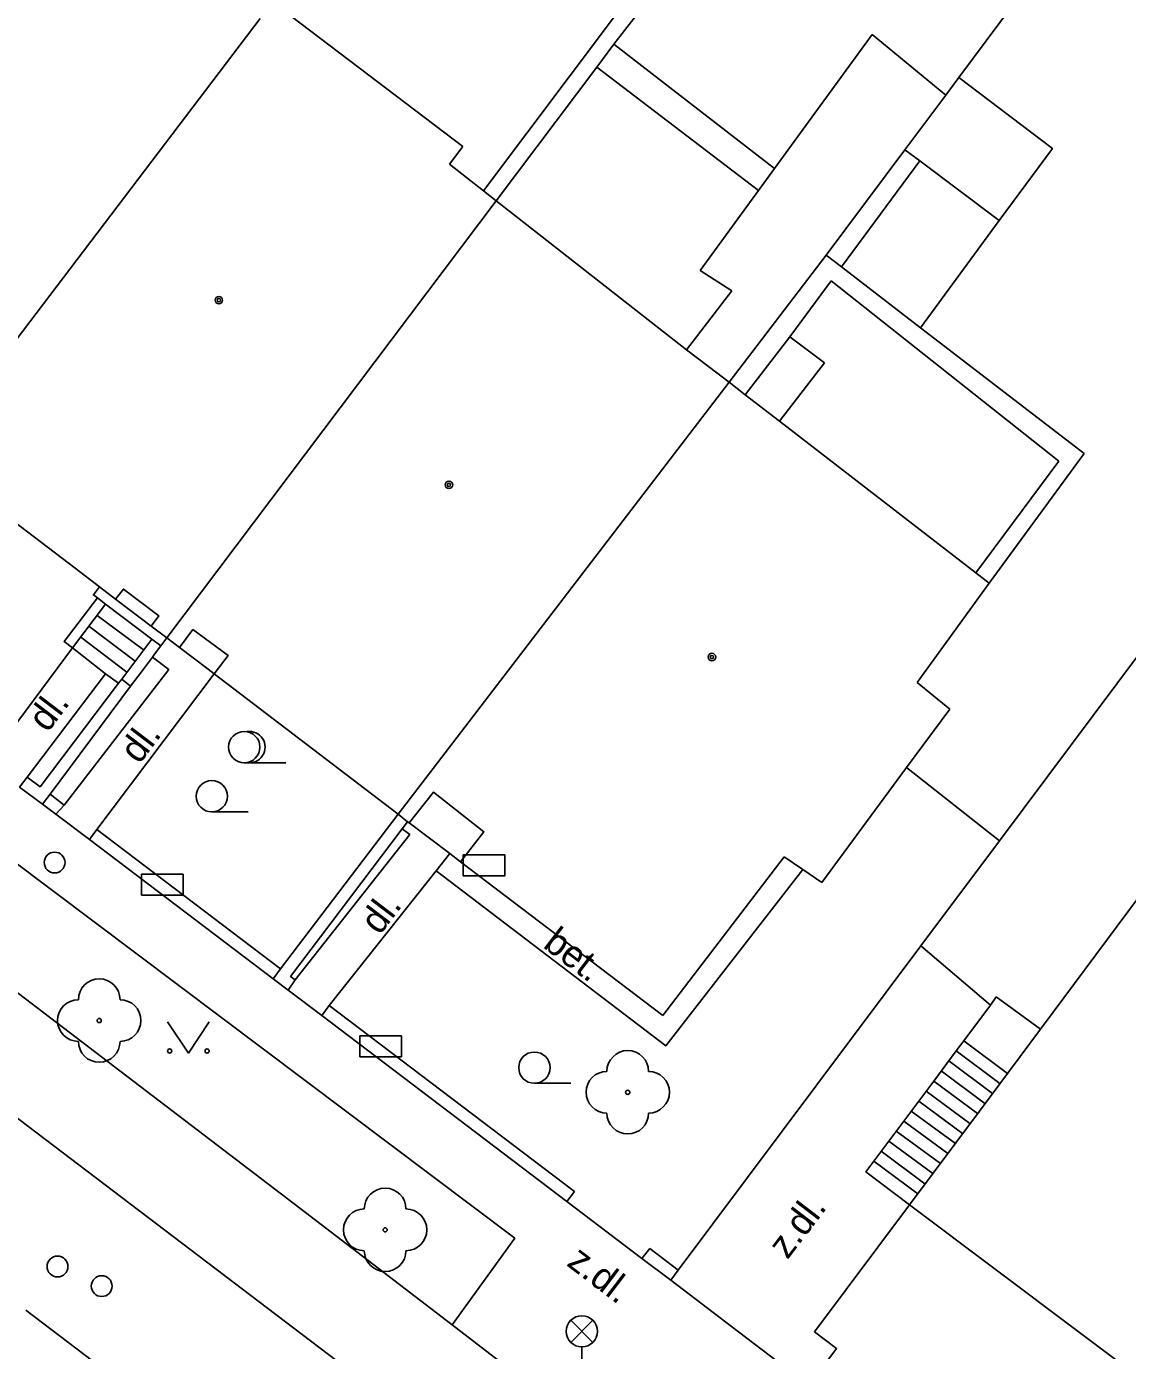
# Model space of a CAD drawing. Extents: x -595546 to -593986, y -1160845 to -1159202.
# Drawn here: x -595175.91 to -595149.49, y -1160755.88 to -1160724.12 of the extents above; entities that cross this region are included whole.
import ezdxf

# ---------------------------------------------------------------- set-up
doc = ezdxf.new("R2010")
doc.units = 0
for name, color, linetype in [('DOP - kresba z DSPS bez souradnic', 7, 'Continuous'), ('DOP - rozhrani ploch obecne', 7, 'Continuous'), ('Level 22', 7, 'Continuous'), ('Level 24', 7, 'Continuous'), ('Level 28', 7, 'Continuous'), ('Level 33', 7, 'Continuous'), ('Level 36', 7, 'Continuous'), ('Level 39', 7, 'Continuous'), ('Specificka linie pasportu komunikaci', 7, 'Continuous'), ('TM - budovy zdene_ betonove - NP', 7, 'Continuous'), ('TM - budovy zdene_ betonove - VP', 7, 'Continuous'), ('TM - chodniky - VP', 7, 'Continuous'), ('TM - komunikace - VP', 7, 'Continuous'), ('TM - letecke snimky - pomocna linie', 7, 'Continuous'), ('TM - plot drateny_ kovovy - VP', 7, 'Continuous'), ('TM - podezdivka plotu - VP', 7, 'Continuous'), ('TM - popis povrchu', 7, 'Continuous'), ('TM - rozhrani mezi zpev. plochami mezi sebou - VP', 7, 'Continuous'), ('TM - rozhrani ploch obecne - VP', 7, 'Continuous'), ('TM - schody - VP', 7, 'Continuous'), ('TM - vjezd na pozemek', 7, 'Continuous')]:
    doc.layers.add(name, color=color, linetype=linetype)

msp = doc.modelspace()

# ---------------------------------------------------------------- linework, layer by layer
at = {"layer": 'DOP - kresba z DSPS bez souradnic'}
for points in [[(-595164.94, -1160728.07), (-595161.82, -1160723.92)], [(-595158.34, -1160728.06), (-595162.22, -1160725.1)], [(-595154.83, -1160727.08), (-595154.47, -1160727.35)], [(-595157.96, -1160727.53), (-595158.34, -1160728.06)], [(-595154.47, -1160727.35), (-595156.35, -1160729.89)], [(-595154.47, -1160727.35), (-595152.57, -1160728.78)], [(-595159.74, -1160729.98), (-595158.34, -1160728.06)], [(-595152.57, -1160728.78), (-595154.46, -1160731.35)], [(-595158.98, -1160730.47), (-595159.74, -1160729.98)], [(-595160.07, -1160731.88), (-595158.98, -1160730.47)], [(-595156.6, -1160730.23), (-595157.59, -1160731.57)], [(-595156.6, -1160730.23), (-595151.14, -1160734.55)], [(-595157.59, -1160731.57), (-595158.66, -1160732.96)], [(-595157.59, -1160731.57), (-595156.76, -1160732.19)], [(-595156.76, -1160732.19), (-595157.84, -1160733.59)], [(-595151.14, -1160734.55), (-595153.13, -1160737.23)]]:
    msp.add_lwpolyline(points, dxfattribs=at)
at = {"layer": 'DOP - rozhrani ploch obecne'}
for points in [[(-595153.54, -1160725.35), (-595140.12, -1160707.34)], [(-595161.25, -1160723.82), (-595161.81, -1160724.55)], [(-595157.96, -1160727.53), (-595155.62, -1160724.32)], [(-595155.62, -1160724.32), (-595153.85, -1160725.77)], [(-595161.81, -1160724.55), (-595162.22, -1160725.1)], [(-595161.81, -1160724.55), (-595157.96, -1160727.53)], [(-595162.22, -1160725.1), (-595164.64, -1160728.31)], [(-595153.85, -1160725.77), (-595153.54, -1160725.35)], [(-595154.83, -1160727.08), (-595153.85, -1160725.77)], [(-595156.72, -1160729.61), (-595154.83, -1160727.08)], [(-595156.72, -1160729.61), (-595159.05, -1160732.66)], [(-595156.35, -1160729.89), (-595156.72, -1160729.61)], [(-595154.46, -1160731.35), (-595156.35, -1160729.89)], [(-595150.53, -1160734.37), (-595154.46, -1160731.35)], [(-595152.81, -1160737.48), (-595150.53, -1160734.37)]]:
    msp.add_lwpolyline(points, dxfattribs=at)
at = {"layer": 'Level 22'}
for centre in [(-595174.16, -1160747.97), (-595161.48, -1160749.69), (-595167.3, -1160752.99)]:
    msp.add_circle(centre, 0.05, dxfattribs=at)
for centre, start, end in [((-595174.16, -1160747.47), 0, 180), ((-595174.66, -1160747.97), 90, 270), ((-595173.66, -1160747.97), 270, 90), ((-595174.16, -1160748.47), 180, 0), ((-595161.48, -1160749.19), 0, 180), ((-595161.98, -1160749.69), 90, 270), ((-595160.98, -1160749.69), 270, 90), ((-595161.48, -1160750.19), 180, 0), ((-595167.3, -1160752.49), 0, 180), ((-595167.8, -1160752.99), 90, 270), ((-595166.8, -1160752.99), 270, 90), ((-595167.3, -1160753.49), 180, 0)]:
    msp.add_arc(centre, 0.5, start, end, dxfattribs=at)
at = {"layer": 'Level 24'}
for points in [[(-595165.427, -1160744.498), (-595164.427, -1160744.498), (-595164.427, -1160743.998), (-595165.427, -1160743.998)], [(-595173.148, -1160744.959), (-595172.148, -1160744.959), (-595172.148, -1160744.459), (-595173.148, -1160744.459)], [(-595167.908, -1160748.839), (-595166.908, -1160748.839), (-595166.908, -1160748.339), (-595167.908, -1160748.339)]]:
    msp.add_lwpolyline(points, close=True, dxfattribs=at)
at = {"layer": 'Level 28'}
for centre in [(-595175.23, -1160744.18), (-595175.16, -1160753.87), (-595174.1, -1160754.34)]:
    msp.add_circle(centre, 0.25, dxfattribs=at)
at = {"layer": 'Level 33'}
for p, q in [((-595162.845, -1160755.69), (-595162.315, -1160755.16)), ((-595162.845, -1160755.16), (-595162.315, -1160755.69)), ((-595162.58, -1160755.8), (-595162.58, -1160756.55))]:
    msp.add_line(p, q, dxfattribs=at)
msp.add_circle((-595162.58, -1160755.425), 0.375, dxfattribs=at)
at = {"layer": 'Level 36'}
for p, q in [((-595170.68, -1160741.785), (-595169.68, -1160741.785)), ((-595171.46, -1160742.965), (-595170.585, -1160742.965)), ((-595163.72, -1160749.475), (-595162.845, -1160749.475))]:
    msp.add_line(p, q, dxfattribs=at)
msp.add_lwpolyline([(-595172.52, -1160748), (-595172.02, -1160748.75), (-595171.52, -1160748)], dxfattribs=at)
for centre, radius in [((-595170.68, -1160741.41), 0.375), ((-595171.46, -1160742.59), 0.375), ((-595172.47, -1160748.7), 0.05), ((-595171.571, -1160748.7), 0.05), ((-595163.72, -1160749.1), 0.375)]:
    msp.add_circle(centre, radius, dxfattribs=at)
msp.add_arc((-595170.555, -1160741.41), 0.375, 260.4059, 99.5941, dxfattribs=at)
at = {"layer": 'Level 39'}
for centre, radius in [((-595171.29, -1160730.69), 0.09), ((-595171.29, -1160730.69), 0.0398), ((-595165.77, -1160735.12), 0.09), ((-595165.77, -1160735.12), 0.0398), ((-595159.46, -1160739.25), 0.09), ((-595159.46, -1160739.25), 0.0398)]:
    msp.add_circle(centre, radius, dxfattribs=at)
at = {"layer": 'Specificka linie pasportu komunikaci'}
msp.add_lwpolyline([(-595154.79, -1160741.9), (-595152.56, -1160743.66)], dxfattribs=at)
at = {"layer": 'TM - budovy zdene_ betonove - NP'}
for points in [[(-595173.77, -1160737.86), (-595173.58, -1160737.62), (-595172.73, -1160738.26), (-595172.91, -1160738.51)], [(-595172.23, -1160739.02), (-595171.91, -1160738.59), (-595171.07, -1160739.21), (-595171.4, -1160739.65)], [(-595166.72, -1160743.23), (-595166.14, -1160742.49), (-595164.93, -1160743.44), (-595165.49, -1160744.16)]]:
    msp.add_lwpolyline(points, dxfattribs=at)
at = {"layer": 'TM - budovy zdene_ betonove - VP'}
for points in [[(-595169.78, -1160723.71), (-595165.44, -1160727)], [(-595170.3, -1160723.93), (-595178.28, -1160734.43)], [(-595165.44, -1160727), (-595165.76, -1160727.43)], [(-595165.76, -1160727.43), (-595164.94, -1160728.07)], [(-595164.94, -1160728.07), (-595164.64, -1160728.31)], [(-595164.64, -1160728.31), (-595172.54, -1160738.79)], [(-595164.64, -1160728.31), (-595160.07, -1160731.88)], [(-595160.07, -1160731.88), (-595159.05, -1160732.66)], [(-595159.05, -1160732.66), (-595166.99, -1160743.02)], [(-595159.05, -1160732.66), (-595158.66, -1160732.96)], [(-595158.66, -1160732.96), (-595157.84, -1160733.59)], [(-595157.84, -1160733.59), (-595153.13, -1160737.23)], [(-595174.74, -1160737.12), (-595178.04, -1160734.61)], [(-595174.15, -1160737.57), (-595174.74, -1160737.12)], [(-595154.54, -1160739.86), (-595152.81, -1160737.48)], [(-595153.13, -1160737.23), (-595152.81, -1160737.48)], [(-595173.77, -1160737.86), (-595174.15, -1160737.57)], [(-595172.91, -1160738.51), (-595173.77, -1160737.86)], [(-595172.54, -1160738.79), (-595172.91, -1160738.51)], [(-595172.54, -1160738.79), (-595172.23, -1160739.02)], [(-595172.23, -1160739.02), (-595171.55, -1160739.54), (-595171.4, -1160739.65)], [(-595171.4, -1160739.65), (-595166.99, -1160743.02)], [(-595153.75, -1160740.5), (-595154.54, -1160739.86)], [(-595154.79, -1160741.9), (-595153.75, -1160740.5)], [(-595156.82, -1160744.66), (-595154.79, -1160741.9)], [(-595151.27, -1160747.77), (-595147.41, -1160742.58)], [(-595166.99, -1160743.02), (-595166.76, -1160743.2)], [(-595166.76, -1160743.2), (-595166.72, -1160743.23)], [(-595166.72, -1160743.23), (-595165.75, -1160743.96)], [(-595165.75, -1160743.96), (-595165.49, -1160744.16)], [(-595160.64, -1160747.85), (-595157.73, -1160744.04)], [(-595157.73, -1160744.04), (-595157.28, -1160744.35)], [(-595165.49, -1160744.16), (-595160.64, -1160747.85)], [(-595157.28, -1160744.35), (-595156.82, -1160744.66)], [(-595151.58, -1160748.18), (-595151.27, -1160747.77)], [(-595153.04, -1160750.14), (-595151.58, -1160748.18)], [(-595154.72, -1160752.39), (-595153.04, -1160750.14)], [(-595148.62, -1160756.97), (-595154.72, -1160752.39)]]:
    msp.add_lwpolyline(points, dxfattribs=at)
at = {"layer": 'TM - chodniky - VP'}
msp.add_lwpolyline([(-595181.17, -1160743.46), (-595180.5, -1160742.5), (-595179.32, -1160741.82), (-595164.19, -1160753.19), (-595165.69, -1160755.27)], dxfattribs=at)
at = {"layer": 'TM - komunikace - VP'}
for points in [[(-595165.69, -1160755.27), (-595169.35, -1160752.47), (-595181.17, -1160743.46)], [(-595159.66, -1160767.27), (-595175.92, -1160754.92)], [(-595162.81, -1160757.48), (-595165.69, -1160755.27)]]:
    msp.add_lwpolyline(points, dxfattribs=at)
at = {"layer": 'TM - letecke snimky - pomocna linie'}
for points in [[(-595152.57, -1160728.78), (-595151.29, -1160727.05), (-595153.54, -1160725.35)], [(-595154.72, -1160752.39), (-595157, -1160755.44)]]:
    msp.add_lwpolyline(points, dxfattribs=at)
at = {"layer": 'TM - plot drateny_ kovovy - VP'}
for points in [[(-595173.7, -1160739.88), (-595175.58, -1160742.36), (-595175.89, -1160742.13)], [(-595175, -1160742.8), (-595175.34, -1160742.54)], [(-595166.89, -1160743.37), (-595166.76, -1160743.2)], [(-595169.81, -1160746.73), (-595174.22, -1160743.39)], [(-595169.46, -1160746.99), (-595169.57, -1160746.91), (-595166.89, -1160743.37)], [(-595162.76, -1160752.07), (-595168.64, -1160747.61)], [(-595160.27, -1160753.96), (-595160.95, -1160753.44)]]:
    msp.add_lwpolyline(points, dxfattribs=at)
at = {"layer": 'TM - podezdivka plotu - VP'}
for points in [[(-595173.41, -1160739.95), (-595175.34, -1160742.54)], [(-595176.07, -1160742.37), (-595175.89, -1160742.13)], [(-595175.52, -1160742.78), (-595176.07, -1160742.37)], [(-595175.34, -1160742.54), (-595175.52, -1160742.78)], [(-595175.2, -1160743.02), (-595175.52, -1160742.78)], [(-595175, -1160742.8), (-595175.2, -1160743.02)], [(-595169.81, -1160746.73), (-595166.99, -1160743.02)], [(-595174.39, -1160743.63), (-595174.22, -1160743.39)], [(-595169.99, -1160746.97), (-595174.39, -1160743.63)], [(-595169.99, -1160746.97), (-595169.81, -1160746.73)], [(-595169.63, -1160747.24), (-595169.99, -1160746.97)], [(-595169.46, -1160746.99), (-595169.63, -1160747.24)], [(-595168.82, -1160747.85), (-595168.64, -1160747.61)], [(-595162.94, -1160752.31), (-595168.82, -1160747.85)], [(-595162.76, -1160752.07), (-595162.94, -1160752.31)], [(-595161.14, -1160753.68), (-595160.95, -1160753.44)], [(-595160.45, -1160754.2), (-595161.14, -1160753.68)]]:
    msp.add_lwpolyline(points, dxfattribs=at)
at = {"layer": 'TM - rozhrani mezi zpev. plochami mezi sebou - VP'}
msp.add_lwpolyline([(-595166.08, -1160744.38), (-595165.75, -1160743.96)], dxfattribs=at)
at = {"layer": 'TM - rozhrani ploch obecne - VP'}
for points in [[(-595174.2, -1160737.83), (-595174.3, -1160737.76), (-595174.15, -1160737.57)], [(-595174.8, -1160739.03), (-595175, -1160738.88), (-595174.2, -1160737.83)], [(-595174.8, -1160739.03), (-595174.01, -1160737.98)], [(-595174.01, -1160737.98), (-595174.2, -1160737.83)], [(-595172.9, -1160738.82), (-595174.01, -1160737.98)], [(-595148.61, -1160738.37), (-595152.56, -1160743.66)], [(-595176.67, -1160741.54), (-595174.8, -1160739.03)], [(-595174.01, -1160739.65), (-595174.8, -1160739.03)], [(-595172.9, -1160738.82), (-595173.62, -1160739.78)], [(-595172.68, -1160738.98), (-595172.9, -1160738.82)], [(-595172.68, -1160738.98), (-595172.83, -1160739.18)], [(-595172.54, -1160738.79), (-595172.68, -1160738.98)], [(-595172.88, -1160739.25), (-595172.49, -1160739.55), (-595175, -1160742.8)], [(-595172.88, -1160739.25), (-595173.12, -1160739.57)], [(-595172.83, -1160739.18), (-595172.88, -1160739.25)], [(-595175.89, -1160742.13), (-595174.01, -1160739.65)], [(-595174.22, -1160743.39), (-595171.4, -1160739.65)], [(-595174.01, -1160739.65), (-595173.7, -1160739.88)], [(-595173.12, -1160739.57), (-595173.41, -1160739.95)], [(-595173.62, -1160739.78), (-595173.7, -1160739.88)], [(-595173.62, -1160739.78), (-595173.41, -1160739.95)], [(-595151.01, -1160766.37), (-595152.47, -1160768.29), (-595167.23, -1160757.07), (-595185.77, -1160742.99), (-595187.03, -1160742.03)], [(-595166.89, -1160743.37), (-595166.71, -1160743.51), (-595169.46, -1160746.99)], [(-595152.56, -1160743.66), (-595154.45, -1160746.18)], [(-595168.64, -1160747.61), (-595166.08, -1160744.38)], [(-595166.08, -1160744.38), (-595160.57, -1160748.58), (-595157.28, -1160744.35)], [(-595154.45, -1160746.18), (-595160.27, -1160753.96)], [(-595154.45, -1160746.18), (-595152.78, -1160747.6)], [(-595152.78, -1160747.6), (-595153.42, -1160748.46), (-595153.6, -1160748.7), (-595154.14, -1160749.42), (-595154.86, -1160750.38)], [(-595152.64, -1160747.4), (-595152.78, -1160747.6)], [(-595152.64, -1160747.4), (-595151.58, -1160748.18)], [(-595155.77, -1160751.6), (-595154.86, -1160750.38)], [(-595155.77, -1160751.6), (-595154.72, -1160752.39)], [(-595160.27, -1160753.96), (-595160.45, -1160754.2)], [(-595157, -1160755.44), (-595156.47, -1160755.84), (-595157, -1160756.55)]]:
    msp.add_lwpolyline(points, dxfattribs=at)
at = {"layer": 'TM - schody - VP'}
for points in [[(-595174.21, -1160738.25), (-595173.1, -1160739.08)], [(-595174.41, -1160738.51), (-595173.3, -1160739.35)], [(-595174.6, -1160738.77), (-595173.5, -1160739.61)], [(-595153.42, -1160748.46), (-595152.37, -1160749.24)], [(-595153.6, -1160748.7), (-595152.55, -1160749.48)], [(-595153.96, -1160749.18), (-595152.91, -1160749.96)], [(-595153.78, -1160748.94), (-595152.73, -1160749.72)], [(-595154.14, -1160749.42), (-595153.09, -1160750.2)], [(-595154.32, -1160749.66), (-595153.27, -1160750.44)], [(-595154.68, -1160750.14), (-595153.62, -1160750.92)], [(-595154.5, -1160749.9), (-595153.45, -1160750.68)], [(-595154.86, -1160750.38), (-595153.8, -1160751.16)], [(-595155.04, -1160750.62), (-595153.98, -1160751.4)], [(-595155.4, -1160751.1), (-595154.35, -1160751.89)], [(-595155.22, -1160750.86), (-595154.16, -1160751.64)], [(-595155.58, -1160751.34), (-595154.52, -1160752.13)]]:
    msp.add_lwpolyline(points, dxfattribs=at)
at = {"layer": 'TM - vjezd na pozemek'}
for points in [[(-595174.39, -1160743.63), (-595175.2, -1160743.02)], [(-595168.82, -1160747.85), (-595169.63, -1160747.24)], [(-595162.94, -1160752.31), (-595161.14, -1160753.68)], [(-595157.69, -1160756.3), (-595158.82, -1160755.44), (-595160.45, -1160754.2)]]:
    msp.add_lwpolyline(points, dxfattribs=at)

# ---------------------------------------------------------------- texts
at = {"layer": 'TM - popis povrchu'}
for s, rotation, p in [('dl.', 52.7371, (-595175.4, -1160741.08)), ('dl.', 52.7371, (-595173.2, -1160741.84)), ('dl.', 52.7371, (-595167.43, -1160745.94)), ('bet.', 322.7371, (-595163.54, -1160746.2)), ('z.dl.', 52.63, (-595157.65, -1160753.72)), ('z.dl.', 322.7371, (-595162.97, -1160753.83))]:
    msp.add_text(s, height=0.65, rotation=rotation, dxfattribs=at).set_placement(p)

doc.saveas('drawing.dxf')
